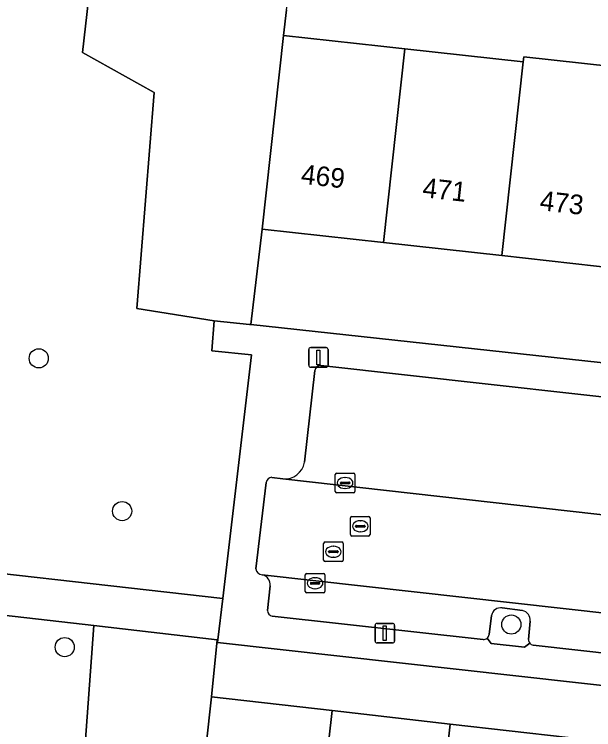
# Model space of a CAD drawing. Extents: x 161928 to 163071, y 386474 to 387428.
# Drawn here: x 162042.88 to 162072.46, y 387040.09 to 387076.6 of the extents above; entities that cross this region are included whole.
import ezdxf

# ---------------------------------------------------------------- set-up
doc = ezdxf.new("R2010")
doc.units = 0
for name, color, linetype in [('IMGEO_Boom', 7, 'Continuous'), ('IMGEO_Erf', 7, 'Continuous'), ('IMGEO_Groenvoorziening', 7, 'Continuous'), ('IMGEO_Hek', 7, 'Continuous'), ('IMGEO_Kolk', 7, 'Continuous'), ('IMGEO_Lichtmast', 7, 'Continuous'), ('IMGEO_Pand', 7, 'Continuous'), ('IMGEO_Pand_nummerreeks', 7, 'Continuous'), ('IMGEO_Parkeervlak_open', 7, 'Continuous'), ('IMGEO_Rijbaan_lokaal_open', 7, 'Continuous'), ('IMGEO_Rioolput', 7, 'Continuous'), ('IMGEO_Voetpad_open', 7, 'Continuous')]:
    doc.layers.add(name, color=color, linetype=linetype)

msp = doc.modelspace()

# ---------------------------------------------------------------- linework, layer by layer
at = {"layer": 'IMGEO_Boom'}
for centre in [(162044.124, 387059.042), (162048.382, 387051.245), (162068.251, 387045.455), (162045.45, 387044.305)]:
    msp.add_circle(centre, 0.489, dxfattribs=at)
at = {"layer": 'IMGEO_Erf'}
for points in [[(162056.78, 387076.828), (162056.626, 387075.526), (162061.596, 387074.975), (162062.813, 387074.84), (162068.857, 387074.171), (162068.886, 387074.43), (162074.93, 387073.76)], [(162073.806, 387063.615), (162067.762, 387064.284), (162061.718, 387064.954), (162055.525, 387065.64), (162054.959, 387060.765), (162093.91, 387056.533)], [(162092.941, 387040.089), (162090.107, 387040.42), (162053.258, 387044.538), (162053.273, 387044.667), (162053.232, 387044.673), (162052.938, 387041.772), (162059.112, 387041.065), (162065.136, 387040.375), (162071.16, 387039.686), (162077.183, 387038.996), (162083.207, 387038.307), (162089.378, 387037.6), (162089.04, 387034.471), (162092.569, 387034.041), (162091.726, 387026.452), (162088.106, 387026.85), (162088.494, 387030.02)]]:
    msp.add_lwpolyline(points, dxfattribs=at)
at = {"layer": 'IMGEO_Groenvoorziening'}
for points in [[(162050.014, 387072.611), (162046.359, 387074.644), (162054.161, 387143.235), (162059.064, 387145.048), (162059.632, 387154.151), (162065.287, 387153.527), (162067.023, 387167.532), (162049.139, 387169.476), (162047.073, 387170.133), (162044.069, 387170.473), (162030.578, 387050.379), (162035.452, 387048.827), (162053.523, 387046.789), (162054.986, 387059.213), (162052.968, 387059.431), (162053.084, 387060.96), (162049.139, 387061.592)], [(162037.211, 387000), (162041.063, 387035.1), (162045.102, 387036.139), (162045.708, 387036.565), (162046.153, 387037.158), (162046.393, 387037.86), (162046.424, 387038.411), (162046.934, 387045.4), (162035.158, 387046.758), (162030.117, 387046.418), (162029.975, 387044.666), (162027.624, 387041.734), (162022.876, 387000), (162016.546, 386941.814), (162020.393, 386940.366), (162041.516, 386937.945), (162043.328, 386951.783), (162043.041, 386951.82), (162037.358, 386952.645), (162038.198, 386963.911), (162033.361, 386966.426)]]:
    msp.add_lwpolyline(points, close=True, dxfattribs=at)
for points in [[(162054.161, 387143.235), (162046.359, 387074.644), (162050.014, 387072.611), (162049.139, 387061.592), (162053.084, 387060.96), (162054.883, 387060.773), (162054.959, 387060.765), (162055.525, 387065.64), (162056.626, 387075.526), (162056.78, 387076.828)], [(162068.823, 387046.177), (162067.787, 387046.302)], [(162067.242, 387045.92), (162067.114, 387044.944)], [(162052.105, 387034.212), (162052.938, 387041.772), (162053.232, 387044.673), (162046.934, 387045.4), (162046.424, 387038.411)], [(162069.123, 387044.7), (162069.22, 387045.629)], [(162067.016, 387044.763), (162067.228, 387044.488), (162068.917, 387044.305), (162069.191, 387044.504)]]:
    msp.add_lwpolyline(points, dxfattribs=at)
for centre, radius, start, end in [((162067.707, 387045.836), 0.473, 80.2869, 169.7677), ((162068.695, 387045.666), 0.527, 355.942, 75.9011), ((162066.834, 387044.978), 0.282, 310.1383, 352.9963), ((162069.416, 387044.692), 0.293, 178.4039, 219.8634)]:
    msp.add_arc(centre, radius, start, end, dxfattribs=at)
at = {"layer": 'IMGEO_Hek'}
msp.add_lwpolyline([(162056.626, 387075.526), (162057.948, 387086.72)], dxfattribs=at)
at = {"layer": 'IMGEO_Kolk'}
for p, q in [((162059.263, 387052.254), (162059.263, 387053.106)), ((162059.338, 387053.18), (162060.19, 387053.18)), ((162060.264, 387053.106), (162060.264, 387052.254)), ((162059.522, 387052.674), (162059.522, 387052.686)), ((162059.565, 387052.723), (162059.963, 387052.723)), ((162059.751, 387052.96), (162059.776, 387052.96)), ((162060.006, 387052.686), (162060.006, 387052.674)), ((162059.96, 387052.637), (162059.562, 387052.637)), ((162059.774, 387052.4), (162059.749, 387052.4)), ((162060.19, 387052.18), (162059.338, 387052.18)), ((162057.732, 387047.14), (162057.732, 387047.992)), ((162057.807, 387048.066), (162058.659, 387048.066)), ((162058.733, 387047.992), (162058.733, 387047.14)), ((162057.991, 387047.56), (162057.991, 387047.572)), ((162058.034, 387047.609), (162058.432, 387047.609)), ((162058.22, 387047.846), (162058.245, 387047.846)), ((162058.475, 387047.572), (162058.475, 387047.56)), ((162058.429, 387047.523), (162058.031, 387047.523)), ((162058.243, 387047.286), (162058.218, 387047.286)), ((162058.659, 387047.066), (162057.807, 387047.066))]:
    msp.add_line(p, q, dxfattribs=at)
for points in [[(162059.263, 387052.254), (162059.263, 387053.106)], [(162059.338, 387053.18), (162060.19, 387053.18)], [(162060.264, 387053.106), (162060.264, 387052.254)], [(162060.19, 387052.18), (162059.338, 387052.18)], [(162057.732, 387047.14), (162057.732, 387047.992)], [(162057.807, 387048.066), (162058.659, 387048.066)], [(162058.733, 387047.992), (162058.733, 387047.14)], [(162058.659, 387047.066), (162057.807, 387047.066)]]:
    msp.add_lwpolyline(points, dxfattribs=at)
for centre, radius, start, end in [((162059.34, 387053.104), 0.0765, 91.552, 178.448), ((162059.34, 387053.104), 0.0765, 91.552, 178.448), ((162060.188, 387053.104), 0.0765, 1.552, 88.448), ((162060.188, 387053.104), 0.0765, 1.552, 88.448), ((162059.562, 387052.683), 0.0403, 85.8775, 175.7526), ((162059.967, 387052.685), 0.0386, 1.7309, 96.639), ((162059.559, 387052.673), 0.0366, 178.938, 274.7102), ((162059.963, 387052.68), 0.043, 264.8664, 352.4533), ((162059.34, 387052.256), 0.0765, 181.552, 268.448), ((162059.34, 387052.256), 0.0765, 181.552, 268.448), ((162060.188, 387052.256), 0.0765, 271.552, 358.448), ((162060.188, 387052.256), 0.0765, 271.552, 358.448), ((162057.809, 387047.99), 0.0765, 91.552, 178.448), ((162057.809, 387047.99), 0.0765, 91.552, 178.448), ((162058.657, 387047.99), 0.0765, 1.552, 88.448), ((162058.657, 387047.99), 0.0765, 1.552, 88.448), ((162058.031, 387047.569), 0.0403, 85.8775, 175.7526), ((162058.436, 387047.571), 0.0386, 1.7309, 96.639), ((162058.028, 387047.559), 0.0366, 178.938, 274.7102), ((162058.432, 387047.566), 0.043, 264.8664, 352.4533), ((162057.809, 387047.142), 0.0765, 181.552, 268.448), ((162057.809, 387047.142), 0.0765, 181.552, 268.448), ((162058.657, 387047.142), 0.0765, 271.552, 358.448), ((162058.657, 387047.142), 0.0765, 271.552, 358.448)]:
    msp.add_arc(centre, radius, start, end, dxfattribs=at)
for centre, major_axis, ratio, start_param, end_param in [((162059.75, 387052.68), (-0.387, 0.002), 0.722429, 4.712389, 7.853982), ((162059.775, 387052.68), (-0.39, 0.002), 0.717154, 1.570796, 4.712389), ((162058.219, 387047.566), (-0.387, 0.002), 0.722429, 4.712389, 7.853982), ((162058.244, 387047.566), (-0.39, 0.002), 0.717154, 1.570796, 4.712389)]:
    msp.add_ellipse(centre, major_axis=major_axis, ratio=ratio, start_param=start_param, end_param=end_param, dxfattribs=at)
at = {"layer": 'IMGEO_Lichtmast'}
for p, q in [((162057.909, 387058.692), (162057.909, 387059.492)), ((162057.909, 387059.492), (162057.909, 387058.692)), ((162058.009, 387059.592), (162058.799, 387059.592)), ((162058.799, 387059.592), (162058.009, 387059.592)), ((162058.899, 387059.492), (162058.899, 387058.692)), ((162058.899, 387058.692), (162058.899, 387059.492)), ((162058.799, 387058.592), (162058.009, 387058.592)), ((162058.009, 387058.592), (162058.799, 387058.592)), ((162061.297, 387044.614), (162061.297, 387045.414)), ((162061.297, 387045.414), (162061.297, 387044.614)), ((162061.397, 387045.514), (162062.187, 387045.514)), ((162062.187, 387045.514), (162061.397, 387045.514)), ((162062.287, 387045.414), (162062.287, 387044.614)), ((162062.287, 387044.614), (162062.287, 387045.414)), ((162062.187, 387044.514), (162061.397, 387044.514)), ((162061.397, 387044.514), (162062.187, 387044.514))]:
    msp.add_line(p, q, dxfattribs=at)
for points in [[(162058.329, 387059.467), (162058.479, 387059.467), (162058.479, 387058.717), (162058.329, 387058.717), (162058.329, 387059.467)], [(162061.717, 387045.389), (162061.867, 387045.389), (162061.867, 387044.639), (162061.717, 387044.639), (162061.717, 387045.389)]]:
    msp.add_lwpolyline(points, dxfattribs=at)
for centre, start, end in [((162058.009, 387059.492), 90, 180), ((162058.009, 387059.492), 90, 180), ((162058.799, 387059.492), 0, 90), ((162058.799, 387059.492), 360, 90), ((162058.009, 387058.692), 180, 270), ((162058.009, 387058.692), 180, 270), ((162058.799, 387058.692), 270, 0), ((162058.799, 387058.692), 270, 0), ((162061.397, 387045.414), 90, 180), ((162061.397, 387045.414), 90, 180), ((162062.187, 387045.414), 0, 90), ((162062.187, 387045.414), 360, 90), ((162061.397, 387044.614), 180, 270), ((162061.397, 387044.614), 180, 270), ((162062.187, 387044.614), 270, 0), ((162062.187, 387044.614), 270, 0)]:
    msp.add_arc(centre, 0.1, start, end, dxfattribs=at)
at = {"layer": 'IMGEO_Pand'}
for points in [[(162055.525, 387065.64), (162061.718, 387064.954), (162062.813, 387074.84), (162061.596, 387074.975), (162056.626, 387075.526)], [(162061.718, 387064.954), (162067.762, 387064.284), (162068.857, 387074.171), (162062.813, 387074.84)], [(162074.67, 387071.416), (162074.93, 387073.76), (162068.886, 387074.43), (162068.857, 387074.171), (162067.762, 387064.284), (162073.806, 387063.615)], [(162052.105, 387034.212), (162051.69, 387030.446), (162057.792, 387029.743), (162058.247, 387033.505), (162059.112, 387041.065), (162052.938, 387041.772)], [(162058.247, 387033.505), (162064.271, 387032.811), (162065.136, 387040.375), (162059.112, 387041.065)], [(162063.841, 387029.051), (162069.881, 387028.361), (162070.294, 387032.117), (162071.16, 387039.686), (162065.136, 387040.375), (162064.271, 387032.811)]]:
    msp.add_lwpolyline(points, close=True, dxfattribs=at)
at = {"layer": 'IMGEO_Parkeervlak_open'}
for points in [[(162080.189, 387056.264), (162058.518, 387058.674)], [(162058.22, 387058.421), (162057.687, 387053.736)], [(162056.591, 387052.9), (162080.632, 387050.187)], [(162094.381, 387043.64), (162094.028, 387043.682), (162055.527, 387047.995)], [(162055.94, 387047.433), (162055.799, 387046.174)], [(162067.787, 387046.302), (162068.823, 387046.177)], [(162056.049, 387045.887), (162066.811, 387044.695)], [(162067.114, 387044.944), (162067.242, 387045.92)], [(162069.22, 387045.629), (162069.123, 387044.7)], [(162069.371, 387044.404), (162080.154, 387043.201)]]:
    msp.add_lwpolyline(points, dxfattribs=at)
for centre, radius, start, end in [((162058.511, 387058.38), 0.294, 88.6409, 172.0212), ((162056.696, 387053.899), 1.005, 264.0213, 350.6496), ((162055.434, 387047.494), 0.51, 353.1506, 79.4719), ((162056.11, 387046.193), 0.312, 183.4434, 258.6735), ((162067.707, 387045.836), 0.473, 80.2869, 169.7677), ((162068.695, 387045.666), 0.527, 355.942, 75.9011), ((162066.83, 387044.982), 0.288, 266.3123, 310.3898), ((162066.834, 387044.978), 0.282, 310.1383, 352.9963), ((162069.416, 387044.692), 0.293, 178.4039, 219.8634), ((162069.41, 387044.686), 0.285, 219.7841, 262.1067)]:
    msp.add_arc(centre, radius, start, end, dxfattribs=at)
at = {"layer": 'IMGEO_Rijbaan_lokaal_open'}
for points in [[(162055.731, 387052.708), (162055.208, 387048.301)], [(162094.599, 387048.655), (162092.891, 387048.842), (162082.851, 387049.942), (162081.394, 387050.101), (162080.632, 387050.187), (162056.591, 387052.9), (162056.026, 387052.968)], [(162055.527, 387047.995), (162094.028, 387043.682), (162094.599, 387048.655)]]:
    msp.add_lwpolyline(points, dxfattribs=at)
for centre, radius, start, end in [((162056.037, 387052.659), 0.31, 91.9796, 170.8035), ((162055.566, 387048.355), 0.362, 188.5784, 263.8047)]:
    msp.add_arc(centre, radius, start, end, dxfattribs=at)
at = {"layer": 'IMGEO_Rioolput'}
for p, q in [((162060.04, 387050.046), (162060.04, 387050.898)), ((162060.115, 387050.972), (162060.967, 387050.972)), ((162061.041, 387050.898), (162061.041, 387050.046)), ((162060.342, 387050.515), (162060.74, 387050.515)), ((162060.528, 387050.752), (162060.553, 387050.752)), ((162060.299, 387050.466), (162060.299, 387050.478)), ((162060.737, 387050.429), (162060.339, 387050.429)), ((162060.551, 387050.192), (162060.526, 387050.192)), ((162060.783, 387050.478), (162060.783, 387050.466)), ((162060.967, 387049.972), (162060.115, 387049.972)), ((162058.666, 387048.744), (162058.666, 387049.596)), ((162058.741, 387049.67), (162059.593, 387049.67)), ((162059.154, 387049.45), (162059.179, 387049.45)), ((162059.667, 387049.596), (162059.667, 387048.744)), ((162058.925, 387049.164), (162058.925, 387049.176)), ((162059.363, 387049.127), (162058.965, 387049.127)), ((162058.968, 387049.213), (162059.366, 387049.213)), ((162059.409, 387049.176), (162059.409, 387049.164)), ((162059.593, 387048.67), (162058.741, 387048.67)), ((162059.177, 387048.89), (162059.152, 387048.89))]:
    msp.add_line(p, q, dxfattribs=at)
for points in [[(162060.04, 387050.046), (162060.04, 387050.898)], [(162060.115, 387050.972), (162060.967, 387050.972)], [(162061.041, 387050.898), (162061.041, 387050.046)], [(162060.967, 387049.972), (162060.115, 387049.972)], [(162058.666, 387048.744), (162058.666, 387049.596)], [(162058.741, 387049.67), (162059.593, 387049.67)], [(162059.667, 387049.596), (162059.667, 387048.744)], [(162059.593, 387048.67), (162058.741, 387048.67)]]:
    msp.add_lwpolyline(points, dxfattribs=at)
for centre, radius, start, end in [((162060.117, 387050.896), 0.0765, 91.552, 178.448), ((162060.117, 387050.896), 0.0765, 91.552, 178.448), ((162060.965, 387050.896), 0.0765, 1.552, 88.448), ((162060.965, 387050.896), 0.0765, 1.552, 88.448), ((162060.339, 387050.475), 0.0403, 85.8775, 175.7526), ((162060.744, 387050.477), 0.0386, 1.7309, 96.639), ((162060.336, 387050.465), 0.0366, 178.938, 274.7102), ((162060.74, 387050.472), 0.043, 264.8664, 352.4533), ((162060.117, 387050.048), 0.0765, 181.552, 268.448), ((162060.117, 387050.048), 0.0765, 181.552, 268.448), ((162060.965, 387050.048), 0.0765, 271.552, 358.448), ((162060.965, 387050.048), 0.0765, 271.552, 358.448), ((162058.743, 387049.594), 0.0765, 91.552, 178.448), ((162058.743, 387049.594), 0.0765, 91.552, 178.448), ((162059.591, 387049.594), 0.0765, 1.552, 88.448), ((162059.591, 387049.594), 0.0765, 1.552, 88.448), ((162058.965, 387049.173), 0.0403, 85.8775, 175.7526), ((162058.962, 387049.163), 0.0366, 178.938, 274.7102), ((162059.366, 387049.17), 0.043, 264.8664, 352.4533), ((162059.37, 387049.175), 0.0386, 1.7309, 96.639), ((162058.743, 387048.746), 0.0765, 181.552, 268.448), ((162058.743, 387048.746), 0.0765, 181.552, 268.448), ((162059.591, 387048.746), 0.0765, 271.552, 358.448), ((162059.591, 387048.746), 0.0765, 271.552, 358.448)]:
    msp.add_arc(centre, radius, start, end, dxfattribs=at)
for centre, major_axis, ratio, start_param, end_param in [((162060.527, 387050.472), (-0.387, 0.002), 0.722429, 4.712389, 7.853982), ((162060.552, 387050.472), (-0.39, 0.002), 0.717154, 1.570796, 4.712389), ((162059.153, 387049.17), (-0.387, 0.002), 0.722429, 4.712389, 7.853982), ((162059.178, 387049.17), (-0.39, 0.002), 0.717154, 1.570796, 4.712389)]:
    msp.add_ellipse(centre, major_axis=major_axis, ratio=ratio, start_param=start_param, end_param=end_param, dxfattribs=at)
at = {"layer": 'IMGEO_Voetpad_open'}
for points in [[(162093.91, 387056.533), (162054.959, 387060.765), (162054.883, 387060.773), (162053.084, 387060.96), (162052.968, 387059.431), (162054.986, 387059.213), (162053.523, 387046.789), (162053.273, 387044.667), (162053.258, 387044.538), (162090.107, 387040.42), (162092.941, 387040.089), (162093.455, 387041.698), (162082.699, 387042.892)], [(162058.518, 387058.674), (162080.189, 387056.264)], [(162057.687, 387053.736), (162058.22, 387058.421)], [(162055.208, 387048.301), (162055.731, 387052.708)], [(162056.026, 387052.968), (162056.591, 387052.9)], [(162055.799, 387046.174), (162055.94, 387047.433)], [(162066.811, 387044.695), (162056.049, 387045.887)], [(162069.191, 387044.504), (162068.917, 387044.305), (162067.228, 387044.488), (162067.016, 387044.763)], [(162080.154, 387043.201), (162069.371, 387044.404)]]:
    msp.add_lwpolyline(points, dxfattribs=at)
msp.add_lwpolyline([(162035.452, 387048.827), (162030.578, 387050.379), (162030.117, 387046.418), (162035.158, 387046.758), (162046.934, 387045.4), (162053.232, 387044.673), (162053.273, 387044.667), (162053.523, 387046.789)], close=True, dxfattribs=at)
for centre, radius, start, end in [((162058.511, 387058.38), 0.294, 88.6409, 172.0212), ((162056.696, 387053.899), 1.005, 264.0213, 350.6496), ((162056.037, 387052.659), 0.31, 91.9796, 170.8035), ((162055.566, 387048.355), 0.362, 188.5784, 263.8047), ((162055.434, 387047.494), 0.51, 353.1506, 79.4719), ((162056.11, 387046.193), 0.312, 183.4434, 258.6735), ((162066.83, 387044.982), 0.288, 266.3123, 310.3898), ((162069.41, 387044.686), 0.285, 219.7841, 262.1067)]:
    msp.add_arc(centre, radius, start, end, dxfattribs=at)

# ---------------------------------------------------------------- texts
at = {"layer": 'IMGEO_Pand_nummerreeks'}
for s, rotation, p in [('469', 353.6789, (162057.479, 387067.959)), ('471', 353.6789, (162063.685, 387067.272)), ('473', 353.6803, (162069.667, 387066.609))]:
    msp.add_text(s, height=1, rotation=rotation, dxfattribs=at).set_placement(p)

doc.saveas('drawing.dxf')
